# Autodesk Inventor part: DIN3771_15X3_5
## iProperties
Created: 2007-03
Part Number: DIN3771_15X3_5
Document SubType Name: Modeling
Designer: Andy Moles
Material: Rubber
Mass: 0.520033 g
Surface Area: 6.39057 cm^2
Volume: 0.559175 cm^3
Density: 0.93 g/cm^3
Author: Andy Moles
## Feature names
1. Base1
